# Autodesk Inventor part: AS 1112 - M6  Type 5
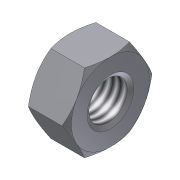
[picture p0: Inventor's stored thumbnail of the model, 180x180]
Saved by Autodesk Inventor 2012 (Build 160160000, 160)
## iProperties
Created: 2007-03
Part Number: AS 1112 - M6  Type 5
Material: Steel, Mild
Description: ISO metric hexagon nuts, including thin nuts, slotted nuts and castle nuts
Document SubType Name: Modeling
Standard: AS 1112
Designer: Designer1
Standards Organization: AS
Language: en-US
Size Designation: M6  Type 5
Categories: <MemberInstance><Categories><Category DisplayName="Fasteners" InternalName="e4da775c-781d-43d5-af7c-5136215cf5a6" Mnemonic="FSTN"><Category DisplayName="Nuts" I
Density: 1 g/cm^3
IsCustomPart: 0
Author: Designer1
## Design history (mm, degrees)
body "Solid1"
workaxis "Work Axis1"
workplane "Work Plane1"
sketch "Sketch1"
  geometry: L1 (-5.774, 0)-(-2.887, 5); L2 (-2.887, 5)-(2.887, 5); L3 (2.887, 5)-(5.774, 0); L4 (5.774, 0)-(2.887, -5); L5 (2.887, -5)-(-2.887, -5); L6 (-2.887, -5)-(-5.774, 0); 2 further points
  constraints: 12 end point, 1 coincident, 1 horizontal, 11 other
  dimensions: "d0" = 11.54701 distance of L3.end L1.start (= 1.1547 x SW)
extrude "Body" new body sketch "Sketch1" distance "d1" = 5.2 (= KOH); taper "d2" = 0 deg
revolve "Chamfer1" stored, may be unused: angle "d7" = 90 deg
sketch "Sketch3"
  geometry: A1 r 5 centre (0, 0) between (-2.5, -4.33) and (2.5, -4.33) reference; 1 further point
  constraints: 1 coincident
hole "Thread" sketch "Sketch3" diameter "d25" = 4.917; stored, may be unused: countersink angle "d29" = 82 deg, drill point angle "d31" = 118 deg; dims "d26" = 6, "d27" = 4, "d28" = 2, "d30" = 8
chamfer "Chamfer2" distance "d8" = 0.54127 (= -0.5 x GD1 + 0.5 x NND); stored, may be unused: angle "d9" = 30 deg, second distance "d40" = 0.54127 (= -0.5 x GD1 + 0.5 x NND)
chamfer "Chamfer3" distance "d10" = 0.54127 (= -0.5 x GD1 + 0.5 x NND); stored, may be unused: angle "d11" = 30 deg, second distance "d41" = 0.54127 (= -0.5 x GD1 + 0.5 x NND)
sketch "Sketch2"
  geometry: L1 (0, 2.887)-(0, 5.774) reference; L2 (0, 5.774)-(5.2, 5.774) reference; L3 (5.2, 2.887)-(5.2, 5.774) reference; L4 (-1.04, 0)-(6.24, 0) reference; L5 (0.447, 5.774)-(0, 5); L6 (4.753, 5.774)-(5.2, 5)
  constraints: 4 end point, 4 point on line
  dimensions: "d3" = 30 deg angle of L1 L5 (= ANG1); "d4" = 30 deg angle of L3 L6 (= ANG2); "d5" = 10 diameter of L5.end L4 (= SW0); "d6" = 10 diameter of L6.end L4 (= SW01)
other parameters: "ANG1" = 30 deg [user parameter; used in 1 equation term], "ANG2" = 30 deg [user parameter; used in 1 equation term], "NND" = 6 [user parameter; used in 4 equation terms], "KOH" = 5.2 [user parameter; used in 1 equation term], "SW0" = 10 (= SW) [user parameter; used in 1 equation term], "SW01" = 10 (= SW) [user parameter; used in 1 equation term], "GD1" = 4.91747 (computed from THREADDIA, PTC, TOA) [user parameter; used in 4 equation terms], "GUL" = 0.54127 (= 0.541266 x PTC) [user parameter], "WFT" = 0.5 [user parameter], "THREADDIA" = 6 [user parameter; used in 1 equation term], "TOA" = 30 deg [user parameter; used in 1 equation term], "PTC" = 1 [user parameter; used in 4 equation terms], "E0" = 11.55 (= 1.155 x SW) [user parameter], "GAL" = 0.54127 (= 0.541266 x PTC) [user parameter]
